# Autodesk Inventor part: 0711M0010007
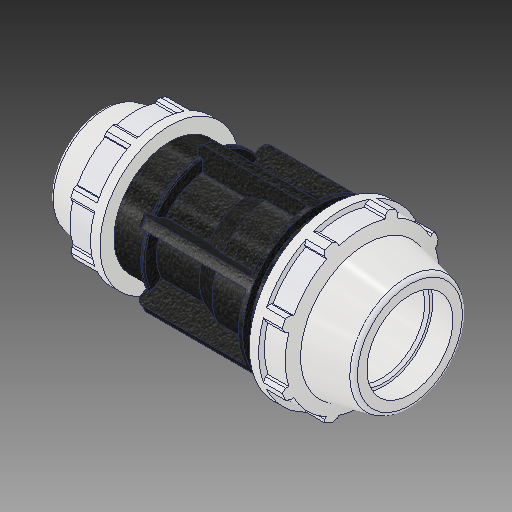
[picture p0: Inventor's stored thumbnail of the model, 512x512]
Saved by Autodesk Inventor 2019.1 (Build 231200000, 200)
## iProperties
Created: 2017-02
Part Number: 0711M0010007
Material: PVC-Piping
Description: PLASSON REDUCING COUPLER 1'' - 3/4''
Document SubType Name: Modeling
Designer: KIM
Mass: 92.6774 g
Surface Area: 199.44 cm^2
Volume: 66.1981 cm^3
Density: 1.4 g/cm^3
Appearance: PTFE
Author: KIM
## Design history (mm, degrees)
derived "0711M0.ipt"
feature "Solid1::0711M0.ipt"
tag "TaggingFeature1"
body "Solid1"
other parameters: "d_" = 33.3, "E_" = 64.008, "H_" = 119, "l_" = 54.102, "d_1" = 26.6, "E_1" = 54.102, "l_1" = 57, "d96" = 6.0878, "d2" = 33.3, "d4" = 9.91667, "d5" = 17, "d7" = 64.008, "d9" = 17, "d11" = 1.7, "d12" = 51.2064, "d13" = 120 deg, "d14" = 43.29, "d15" = 12 deg, "d16" = 57.6072, "d18" = 1.665, "d19" = 35 deg, "d20" = 17.5 deg, "d21" = 59.52744, "d23" = 0, "d25" = 360 deg, "d27" = 1.28016, "d42" = 13.09, "d46" = 0.999, "d51" = 119, "d52" = 41.03448, "d53" = 12 deg, "d54" = 54.102, "d56" = 39.9, "d57" = 26.6, "d58" = 29.97, "d59" = 23.94, "d60" = 48.6918, "d61" = 43.2816, "d62" = 11.9, "d63" = 14.28, "d64" = 120 deg, "d65" = 54.102, "d68" = 8.5, "d74" = 50.31486, "d75" = 35 deg, "d76" = 17.5 deg, "d78" = 0, "d80" = 360 deg, "d85" = 1.08204, "d88" = 0.532, "d93" = 57, "d94" = 44.8056, "d97" = 2.02927, "d98" = 3.6068, "d99" = 0, "d100" = 2.56032, "d102" = 360 deg, "d104" = 2, "d106" = 0, "d107" = 3.6068, "d108" = 0, "d109" = 3.6068, "d110" = 0
